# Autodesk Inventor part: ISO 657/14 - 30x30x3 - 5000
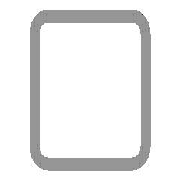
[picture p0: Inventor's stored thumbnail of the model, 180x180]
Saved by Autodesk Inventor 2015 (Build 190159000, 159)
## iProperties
Created: 2014-02
Part Number: ISO 657/14 - 30x30x3 - 5000
Material: Steel, Mild
Description: Hot-rolled steel sections - part 14: hot-finished structrual hollow sections - Dimensions and sectional properties
Document SubType Name: Modeling
Standard: ISO
Designer: 徐冠倫
Standard Revision: Third edition 2000-03-15
Standards Organization: ISO
Language: en-US
Size Designation: 30x30x3
Categories: <MemberInstance><Categories><Category DisplayName="Structural Shapes" InternalName="089c4875-fa83-4c05-b084-43b9cc11f5ed" Mnemonic="GRDR"><CategoryParameter Dis
Stock Number: 30x30x3
Mass: 12110.5 g
Surface Area: 10291.1 cm^2
Volume: 1542.74 cm^3
Density: 7.85 g/cm^3
Appearance: Semi-Polished
_CCFamilyMember: 8
_CCFamilyDisplayName: ISO 657/14 - 2000 (Square) - Hot-rolled steel sections - part 14: hot-finished structrual hollow sections - Dimensions and sectional properties
_FrameMemberDoc: Frame Member File
_Version: 15.0.0
_GetPNFromCC: 1
IsCustomPart: 1
Author: 徐冠倫
G_L: 5000.000 mm
G_W: 30.000 mm
G_H: 30.000 mm
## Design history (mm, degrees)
node "Start plane"
node "End plane"
sketch "Sketch"
  geometry: L1 (-15, -10.5)-(-15, 10.5); L2 (-10.5, 15)-(10.5, 15); L3 (15, 10.5)-(15, -10.5); L4 (10.5, -15)-(-10.5, -15); L5 (-10.5, 12)-(10.5, 12); L6 (12, 10.5)-(12, -10.5); L7 (10.5, -12)-(-10.5, -12); L8 (-12, -10.5)-(-12, 10.5); L9 (0, 22.305)-(0, -22.305) reference; L10 (-22.305, 0)-(22.305, 0) reference; A1 r 4.5 centre (-10.5, -10.5) between (-15, -10.5) and (-10.5, -15); A2 r 4.5 centre (-10.5, 10.5) between (-10.5, 15) and (-15, 10.5); A3 r 4.5 centre (10.5, 10.5) between (15, 10.5) and (10.5, 15); A4 r 4.5 centre (10.5, -10.5) between (10.5, -15) and (15, -10.5); A5 r 1.5 centre (-10.5, 10.5) between (-10.5, 12) and (-12, 10.5); A6 r 1.5 centre (10.5, 10.5) between (12, 10.5) and (10.5, 12); A7 r 1.5 centre (10.5, -10.5) between (10.5, -12) and (12, -10.5); A8 r 1.5 centre (-10.5, -10.5) between (-12, -10.5) and (-10.5, -12)
  constraints: 16 end point, 16 point on circle, 8 centre point, 8 tangent, 4 parallel, 3 equal radius, 2 perpendicular, 7 other
  dimensions: "d7" = 4.5 radius of A1 (= G_IR); "d10" = 30 distance between parallel lines of L2 L4 (= G_H); "d11" = 30 distance between parallel lines of L1 L3 (= G_W); "d12" = 3 distance between parallel lines of L3 L6 (= G_T); "d15" = 15 distance between parallel lines of L2 L10 (= 0.5 x d10); "d16" = 15 distance between parallel lines of L9 L3 (= 0.5 x d11)
extrude "Body" new body sketch "Sketch" stored distance "d3" = 5000 (= G_L); taper "d4" = 0 deg
node "Driven Length"
  sketch "Sketch3"
    geometry: L1 (0, 0)-(10, 0) reference
    constraints: 2 end point, 1 horizontal
  workplane "Work Plane3"
  sketch "Sketch4"
    geometry: L1 (-2, 0)-(12, 0) reference; L2 (-2, 5000)-(12, 5000) reference
    dimensions: "d18" = 5000 distance between parallel lines of L1 L2 (derived)
body "Solid1"
other parameters: "G_W" = 30 [user parameter; used in 1 equation term], "G_H" = 30 [user parameter; used in 1 equation term], "G_T" = 3 [user parameter; used in 1 equation term], "G_IR" = 4.5 [user parameter; used in 1 equation term], "G_L" = 5000 (= d18) [user parameter; used in 1 equation term], "G_OFFSET_START" = 0 [user parameter; used in 1 equation term], "G_OFFSET_END" = 0 [user parameter; used in 1 equation term], "d13" = 0 (computed from G_OFFSET_START), "d17" = 90 deg
